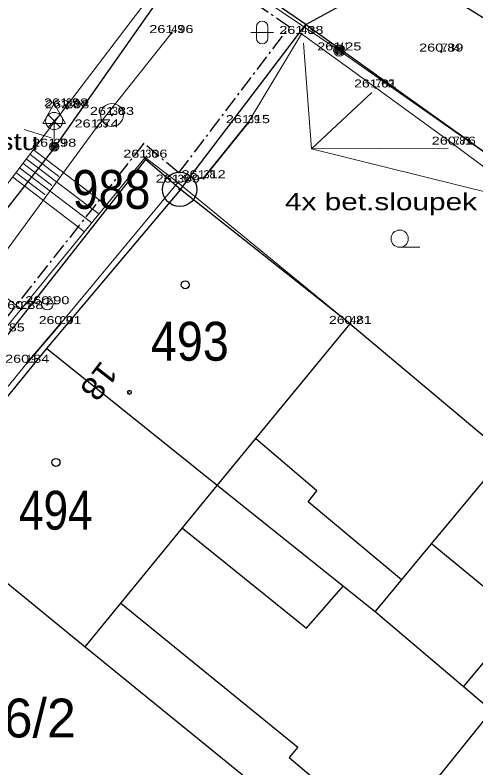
# Model space of a CAD drawing. Extents: x -568530 to -568223, y -1154101 to -1153740.
# Drawn here: x -568429.07 to -568408.9, y -1153975.43 to -1153942.5 of the extents above; entities that cross this region are included whole.
import ezdxf
from ezdxf.enums import TextEntityAlignment as Align

# ---------------------------------------------------------------- set-up
doc = ezdxf.new("R2010")
doc.units = 0
doc.header["$LTSCALE"] = 0.14
doc.header["$PDMODE"] = 32
doc.header["$PDSIZE"] = 0.07
doc.linetypes.add('DOT_DASHED', pattern=[7.7, 5, -1.2, 0.3, -1.2])
for name, color, linetype, lineweight in [('1', 7, 'Continuous', 25), ('10', 7, 'Continuous', 13), ('11', 7, 'Continuous', 13), ('12', 7, 'Continuous', 13), ('15', 7, 'Continuous', 13), ('17', 7, 'Continuous', 13), ('25', 7, 'Continuous', 13), ('27', 7, 'Continuous', 13), ('28', 7, 'Continuous', 13), ('33', 7, 'Continuous', 13), ('34', 7, 'Continuous', 13), ('36', 7, 'Continuous', 13), ('39', 7, 'Continuous', 13), ('4', 7, 'Continuous', 25), ('42', 7, 'Continuous', 13), ('5', 7, 'Continuous', 13), ('52', 7, 'Continuous', 13), ('6', 7, 'DOT_DASHED', 25), ('7', 7, 'Continuous', 13), ('8', 7, 'Continuous', 35)]:
    doc.layers.add(name, color=color, linetype=linetype, lineweight=lineweight)
for name, color, linetype in [('13', 7, 'Continuous'), ('19', 7, 'Continuous'), ('47', 7, 'Continuous')]:
    doc.layers.add(name, color=color, linetype=linetype)

msp = doc.modelspace()

# ---------------------------------------------------------------- linework, layer by layer
at = {"layer": '1'}
msp.add_line((-568414.4, -1153956.01), (-568421.83, -1153950.13), dxfattribs=at)
for points in [[(-568416.35, -1153942.92), (-568421.22, -1153939.56), (-568427.43, -1153948.41), (-568440.04, -1153964.5), (-568454.41, -1153985.19), (-568457.74, -1153989.19)], [(-568421.83, -1153950.13), (-568416.35, -1153942.92), (-568397.86, -1153956.1), (-568381.21, -1153967.57)], [(-568421.83, -1153950.13), (-568423.36, -1153948.82), (-568436.57, -1153965.56)], [(-568421.83, -1153950.13), (-568427.7, -1153957.09), (-568433.42, -1153964.08), (-568426, -1153970.14), (-568416.24, -1153978.06), (-568413.96, -1153980.06), (-568408.2, -1153972.93), (-568413.31, -1153968.6), (-568420.22, -1153963.08), (-568427.7, -1153957.09)], [(-568414.4, -1153956.01), (-568407.59, -1153961.72), (-568387.94, -1153977.62)], [(-568409.44, -1153971.88), (-568406.92, -1153968.85), (-568410.84, -1153965.63), (-568407.59, -1153961.72)]]:
    msp.add_lwpolyline(points, dxfattribs=at)
at = {"layer": '10'}
msp.add_lwpolyline([(-568451.7, -1153980.29), (-568449.61, -1153977.28), (-568446.84, -1153973.45), (-568445.91, -1153972.15), (-568442.46, -1153967.27), (-568439.57, -1153963.38), (-568433.28, -1153955), (-568432.53, -1153954), (-568431.81, -1153953.03), (-568426.84, -1153946.5), (-568420.35, -1153937.98), (-568416.07, -1153932.32)], dxfattribs=at)
at = {"layer": '11'}
for points in [[(-568428.8, -1153955.36), (-568423.37, -1153948.74), (-568421.95, -1153949.83)], [(-568445.13, -1153975.16), (-568443.94, -1153973.66), (-568437.25, -1153965.59), (-568429.61, -1153956.34), (-568428.8, -1153955.36), (-568431.81, -1153953.03)]]:
    msp.add_lwpolyline(points, dxfattribs=at)
for p in [(-568422.23, -1153943.29), (-568416.54, -1153943.33), (-568414.88, -1153944.05), (-568410.42, -1153944.1), (-568413.3, -1153945.67), (-568426.84, -1153946.5), (-568426.79, -1153946.58), (-568424.83, -1153946.87), (-568425.5, -1153947.42), (-568418.88, -1153947.23), (-568409.87, -1153948.17), (-568427.36, -1153948.26), (-568423.37, -1153948.74), (-568421.95, -1153949.83), (-568420.82, -1153949.64), (-568428.8, -1153955.36), (-568427.66, -1153955.15), (-568427.1, -1153956.02), (-568414.4, -1153956.01), (-568428.54, -1153957.71)]:
    msp.add_point(p, dxfattribs=at)
at = {"layer": '15'}
for p, q in [((-568428.276, -1153948.387), (-568425.077, -1153950.821)), ((-568428.579, -1153948.785), (-568425.395, -1153951.208)), ((-568428.428, -1153948.586), (-568427.151, -1153949.557)), ((-568428.73, -1153948.984), (-568427.46, -1153949.951)), ((-568429.033, -1153949.382), (-568427.768, -1153950.344)), ((-568428.882, -1153949.183), (-568425.712, -1153951.595)), ((-568429.185, -1153949.58), (-568426.029, -1153951.982))]:
    msp.add_line(p, q, dxfattribs=at)
at = {"layer": '25'}
for radius in [0.25, 0.2, 0.15, 0.1, 0.05]:
    msp.add_circle((-568414.88, -1153944.05), radius, dxfattribs=at)
at = {"layer": '25', "lineweight": 25}
for centre, radius in [((-568421.87, -1153950.13), 0.75), ((-568421.87, -1153950.13), 0.032), ((-568421.62, -1153954.3), 0.175), ((-568427.28, -1153962.07), 0.175)]:
    msp.add_circle(centre, radius, dxfattribs=at)
at = {"layer": '27'}
msp.add_circle((-568424.83, -1153946.87), 0.5, dxfattribs=at)
at = {"layer": '28'}
msp.add_circle((-568427.66, -1153955.15), 0.25, dxfattribs=at)
at = {"layer": '33'}
for p, q in [((-568427.625, -1153947.4), (-568427.095, -1153946.87)), ((-568427.625, -1153946.87), (-568427.095, -1153947.4)), ((-568427.36, -1153947.51), (-568427.36, -1153948.26))]:
    msp.add_line(p, q, dxfattribs=at)
for centre, radius in [((-568427.36, -1153947.135), 0.375), ((-568427.36, -1153948.26), 0.2), ((-568427.36, -1153948.26), 0.1445), ((-568427.36, -1153948.26), 0.0876)]:
    msp.add_circle(centre, radius, dxfattribs=at)
at = {"layer": '34'}
msp.add_line((-568427.36, -1153947.242), (-568427.36, -1153948.26), dxfattribs=at)
msp.add_lwpolyline([(-568427.86, -1153947.242), (-568426.86, -1153947.242), (-568427.36, -1153946.376)], close=True, dxfattribs=at)
at = {"layer": '36'}
for p, q in [((-568418.508, -1153943.011), (-568418.508, -1153943.511)), ((-568418.008, -1153943.011), (-568418.008, -1153943.511)), ((-568418.758, -1153943.261), (-568417.758, -1153943.261)), ((-568412.237, -1153952.658), (-568411.362, -1153952.658))]:
    msp.add_line(p, q, dxfattribs=at)
msp.add_circle((-568412.2367, -1153952.2829), 0.375, dxfattribs=at)
for centre, start, end in [((-568418.2572, -1153943.013), 0, 180), ((-568418.2572, -1153943.513), 180, 0)]:
    msp.add_arc(centre, 0.25, start, end, dxfattribs=at)
at = {"layer": '39'}
for radius in [0.09, 0.0398]:
    msp.add_circle((-568424.0604, -1153959.0083), radius, dxfattribs=at)
at = {"layer": '4'}
msp.add_line((-568413.31, -1153968.6), (-568410.84, -1153965.63), dxfattribs=at)
for points in [[(-568416.35, -1153942.92), (-568411.96, -1153940.51), (-568386.96, -1153956.01), (-568354.94, -1153977.29), (-568293.66, -1154026.45)], [(-568426, -1153970.14), (-568420.22, -1153963.08), (-568414.4, -1153956.01)], [(-568412.16, -1153967.2), (-568416.24, -1153963.8), (-568415.86, -1153963.31), (-568418.54, -1153961.04)], [(-568421.74, -1153964.94), (-568416.31, -1153969.32), (-568414.71, -1153967.48)], [(-568424.44, -1153968.23), (-568416.69, -1153974.53), (-568417.07, -1153974.98), (-568412.78, -1153978.6)]]:
    msp.add_lwpolyline(points, dxfattribs=at)
at = {"layer": '42'}
for p, q in [((-568427.49, -1153947.866), (-568428.676, -1153947.507)), ((-568416.092, -1153948.348), (-568410.123, -1153948.318)), ((-568416.092, -1153948.348), (-568406.958, -1153950.624))]:
    msp.add_line(p, q, dxfattribs=at)
msp.add_lwpolyline([(-568416.452, -1153943.733), (-568416.092, -1153948.348), (-568413.464, -1153945.886)], dxfattribs=at)
at = {"layer": '5'}
msp.add_lwpolyline([(-568429.736, -1153967.081), (-568433.56, -1153963.86), (-568428.54, -1153957.71), (-568427.1, -1153956.02), (-568421.95, -1153949.83), (-568414.4, -1153956.01)], dxfattribs=at)
at = {"layer": '52'}
msp.add_lwpolyline([(-568440.61, -1153926.76), (-568414.88, -1153944.05), (-568397.12, -1153956.51), (-568380.33, -1153967.93), (-568365.972, -1153978.132)], dxfattribs=at)
at = {"layer": '6'}
for p, q in [((-568423.43, -1153948.11), (-568436.96, -1153965.25)), ((-568421.91, -1153949.41), (-568423.43, -1153948.11))]:
    msp.add_line(p, q, dxfattribs=at)
at = {"layer": '6', "linetype": 'Continuous', "lineweight": 35}
msp.add_line((-568427.1, -1153956.02), (-568428.54, -1153957.71), dxfattribs=at)
at = {"layer": '6'}
msp.add_lwpolyline([(-568421.91, -1153949.41), (-568417.06, -1153943.03), (-568421.5, -1153939.97)], dxfattribs=at)
at = {"layer": '7'}
msp.add_line((-568421.95, -1153949.83), (-568420.82, -1153949.64), dxfattribs=at)
for points in [[(-568430.1, -1153953.68), (-568425.5, -1153947.42), (-568422.23, -1153943.29)], [(-568418.88, -1153947.23), (-568416.54, -1153943.33), (-568413.3, -1153945.67), (-568409.87, -1153948.17), (-568406.63, -1153950.58), (-568397.3, -1153957.22)]]:
    msp.add_lwpolyline(points, dxfattribs=at)
at = {"layer": '8'}
msp.add_line((-568418.88, -1153947.23), (-568420.82, -1153949.64), dxfattribs=at)

# ---------------------------------------------------------------- texts
at = {"layer": '12'}
for s, width, p in [('261.96', 1.35, (-568422.23, -1153943.29)), ('261.38', 1.35, (-568416.54, -1153943.33)), ('261.25', 1.35, (-568414.8805, -1153944.05)), ('260.89', 1.35, (-568410.42, -1153944.1)), ('261.01', 1.3, (-568413.3, -1153945.67)), ('261.98', 1.35, (-568426.84, -1153946.5)), ('262.08', 1.35, (-568426.79, -1153946.58)), ('261.83', 1.35, (-568424.83, -1153946.87)), ('261.74', 1.35, (-568425.5, -1153947.42)), ('261.15', 1.35, (-568418.8805, -1153947.23)), ('260.76', 1.35, (-568409.87, -1153948.17)), ('261.98', 1.35, (-568427.36, -1153948.26)), ('261.06', 1.35, (-568423.37, -1153948.74)), ('261.09', 1.35, (-568421.95, -1153949.83)), ('261.12', 1.35, (-568420.82, -1153949.64)), ('260.88', 1.35, (-568428.8, -1153955.36)), ('260.90', 1.35, (-568427.6595, -1153955.15)), ('260.91', 1.3, (-568427.1, -1153956.02)), ('260.81', 1.3, (-568414.4, -1153956.01)), ('260.85', 1.35, (-568429.6105, -1153956.34)), ('260.84', 1.35, (-568428.54, -1153957.71))]:
    msp.add_text(s, height=0.35, dxfattribs=dict(at, width=width)).set_placement(p, align=Align.CENTER)
at = {"layer": '13'}
for s, p in [('43', (-568422.23, -1153943.29)), ('40', (-568416.54, -1153943.33)), ('32', (-568426.84, -1153946.5)), ('33', (-568426.79, -1153946.58)), ('30', (-568424.83, -1153946.87)), ('35', (-568425.5, -1153947.42)), ('39', (-568418.88, -1153947.23)), ('29', (-568427.36, -1153948.26)), ('36', (-568423.37, -1153948.74)), ('37', (-568421.95, -1153949.83)), ('38', (-568420.82, -1153949.64)), ('22', (-568428.8, -1153955.36)), ('20', (-568427.1, -1153956.02)), ('42', (-568414.4, -1153956.01))]:
    msp.add_text(s, height=0.35, dxfattribs=at).set_placement(p)
for s, width, p in [('41', 0.8, (-568414.88, -1153944.05)), ('784', 1.05, (-568410.42, -1153944.1)), ('782', 1.05, (-568413.3, -1153945.67)), ('781', 0.95, (-568409.87, -1153948.17)), ('21', 0.8, (-568427.66, -1153955.15)), ('19', 0.6, (-568428.54, -1153957.71))]:
    msp.add_text(s, height=0.35, dxfattribs=dict(at, width=width)).set_placement(p)
at = {"layer": '17', "width": 0.9}
msp.add_text('988', height=1.7, dxfattribs=at).set_placement((-568423.145, -1153950.98), align=Align.RIGHT)
at = {"layer": '19'}
for s, width, p in [('493', 0.9, (-568423.13, -1153957.62)), ('494', 0.85, (-568428.9, -1153965.01))]:
    msp.add_text(s, height=1.7, dxfattribs=dict(at, width=width)).set_placement(p)
msp.add_text('496/2', height=1.7, dxfattribs=at).set_placement((-568432.1, -1153974.1))
at = {"layer": '42', "width": 1.3}
for s, p in [('ev.c.mostu', (-568431.204, -1153948.406)), ('4x bet.sloupek', (-568413.0565, -1153951.039))]:
    msp.add_text(s, height=0.75, dxfattribs=at).set_placement(p, align=Align.CENTER)
at = {"layer": '47', "width": 1.1}
msp.add_text('18', height=1, rotation=232.348, dxfattribs=at).set_placement((-568425.284, -1153957.568))

doc.saveas('drawing.dxf')
